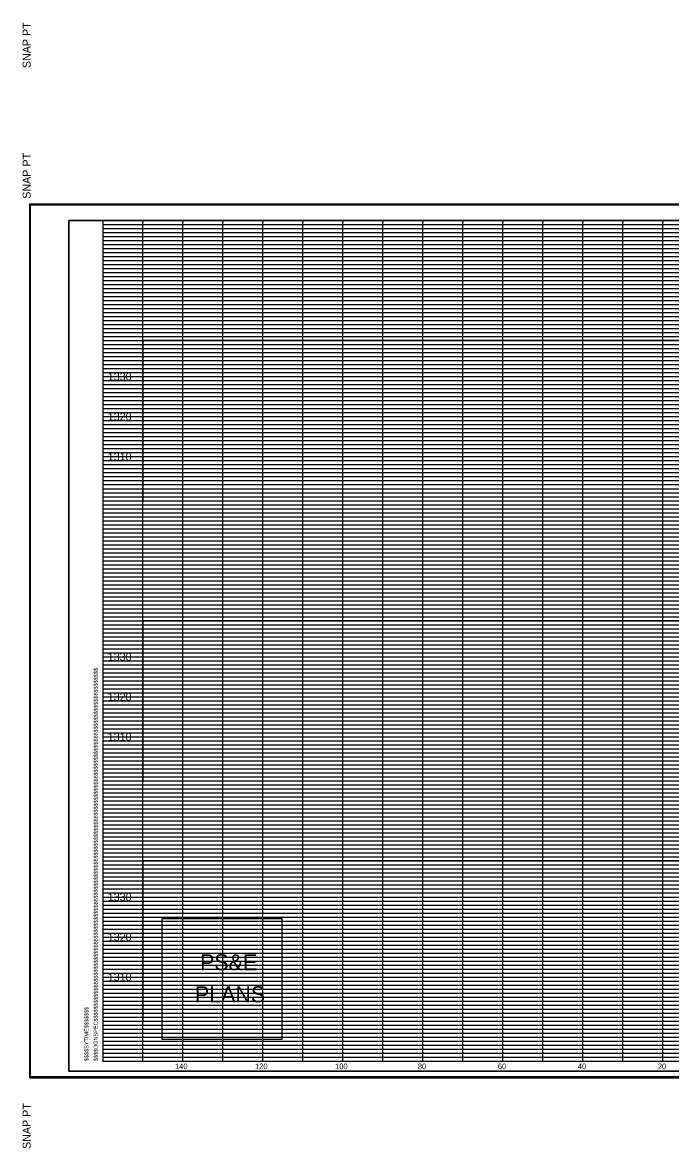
# Model space of a CAD drawing. Extents: x 130 to 1324, y -58 to 2657.
# Drawn here: x 979.9 to 1141.9, y 978.2 to 1259.4 of the extents above; entities that cross this region are included whole.
import ezdxf

# ---------------------------------------------------------------- set-up
doc = ezdxf.new("R2010")
doc.units = 0
for name, color, linetype in [('DESIGN - SCRATCH - User 2', 7, 'Continuous'), ('DESIGN - SHEET - Corner Text', 7, 'Continuous'), ('DESIGN - SHEET - Light Grid', 7, 'Continuous'), ('DESIGN - SHEET - Linework', 7, 'Continuous'), ('DESIGN - SHEET - Plot Shape', 7, 'Continuous'), ('DESIGN - TYPICAL - Finished Grade and Subgrade', 7, 'Continuous')]:
    doc.layers.add(name, color=color, linetype=linetype)

# ---------------------------------------------------------------- blocks, each defined once
blk = doc.blocks.new('XSTSHT')
at = {"layer": 'DESIGN - SHEET - Light Grid'}
for p, q in [((0, 20.9), (8, 20.9)), ((8, 20.9), (16, 20.9)), ((0, 20.8), (8, 20.8)), ((0, 20.7), (8, 20.7)), ((0, 20.6), (8, 20.6)), ((8, 20.8), (16, 20.8)), ((8, 20.7), (16, 20.7)), ((8, 20.6), (16, 20.6)), ((0, 20.5), (8, 20.5)), ((0, 20.4), (8, 20.4)), ((0, 20.3), (8, 20.3)), ((8, 20.5), (16, 20.5)), ((8, 20.4), (16, 20.4)), ((8, 20.3), (16, 20.3)), ((0, 20.2), (8, 20.2)), ((0, 20.1), (8, 20.1)), ((8, 20.2), (16, 20.2)), ((8, 20.1), (16, 20.1)), ((0, 19.9), (8, 19.9)), ((0, 19.8), (8, 19.8)), ((0, 19.7), (8, 19.7)), ((8, 19.9), (16, 19.9)), ((8, 19.8), (16, 19.8)), ((8, 19.7), (16, 19.7)), ((0, 19.6), (8, 19.6)), ((0, 19.5), (8, 19.5)), ((8, 19.6), (16, 19.6)), ((8, 19.5), (16, 19.5)), ((0, 19.4), (8, 19.4)), ((0, 19.3), (8, 19.3)), ((0, 19.2), (8, 19.2)), ((8, 19.4), (16, 19.4)), ((8, 19.3), (16, 19.3)), ((8, 19.2), (16, 19.2)), ((0, 19.1), (8, 19.1)), ((0, 18.9), (8, 18.9)), ((8, 19.1), (16, 19.1)), ((8, 18.9), (16, 18.9)), ((0, 18.8), (8, 18.8)), ((0, 18.7), (8, 18.7)), ((0, 18.6), (8, 18.6)), ((8, 18.8), (16, 18.8)), ((8, 18.7), (16, 18.7)), ((8, 18.6), (16, 18.6)), ((0, 18.5), (8, 18.5)), ((0, 18.4), (8, 18.4)), ((0, 18.3), (8, 18.3)), ((8, 18.5), (16, 18.5)), ((8, 18.4), (16, 18.4)), ((8, 18.3), (16, 18.3)), ((0, 18.2), (8, 18.2)), ((0, 18.1), (8, 18.1)), ((8, 18.2), (16, 18.2)), ((8, 18.1), (16, 18.1)), ((0, 17.9), (8, 17.9)), ((0, 17.8), (8, 17.8)), ((8, 17.9), (16, 17.9)), ((8, 17.8), (16, 17.8)), ((0, 17.7), (8, 17.7)), ((0, 17.6), (8, 17.6)), ((0, 17.5), (8, 17.5)), ((8, 17.7), (16, 17.7)), ((8, 17.6), (16, 17.6)), ((8, 17.5), (16, 17.5)), ((0, 17.4), (8, 17.4)), ((0, 17.3), (8, 17.3)), ((0, 17.2), (8, 17.2)), ((8, 17.4), (16, 17.4)), ((8, 17.3), (16, 17.3)), ((8, 17.2), (16, 17.2)), ((0, 17.1), (8, 17.1)), ((0, 16.9), (8, 16.9)), ((8, 17.1), (16, 17.1)), ((8, 16.9), (16, 16.9)), ((0, 16.8), (8, 16.8)), ((0, 16.7), (8, 16.7)), ((0, 16.6), (8, 16.6)), ((8, 16.8), (16, 16.8)), ((8, 16.7), (16, 16.7)), ((8, 16.6), (16, 16.6)), ((0, 16.5), (8, 16.5)), ((0, 16.4), (8, 16.4)), ((8, 16.5), (16, 16.5)), ((8, 16.4), (16, 16.4)), ((0, 16.3), (8, 16.3)), ((0, 16.2), (8, 16.2)), ((0, 16.1), (8, 16.1)), ((8, 16.3), (16, 16.3)), ((8, 16.2), (16, 16.2)), ((8, 16.1), (16, 16.1)), ((0, 15.9), (8, 15.9)), ((0, 15.8), (8, 15.8)), ((8, 15.9), (16, 15.9)), ((8, 15.8), (16, 15.8)), ((0, 15.7), (8, 15.7)), ((0, 15.6), (8, 15.6)), ((0, 15.5), (8, 15.5)), ((8, 15.7), (16, 15.7)), ((8, 15.6), (16, 15.6)), ((8, 15.5), (16, 15.5)), ((0, 15.4), (8, 15.4)), ((0, 15.3), (8, 15.3)), ((0, 15.2), (8, 15.2)), ((8, 15.4), (16, 15.4)), ((8, 15.3), (16, 15.3)), ((8, 15.2), (16, 15.2)), ((0, 15.1), (8, 15.1)), ((8, 15.1), (16, 15.1)), ((0, 14.9), (8, 14.9)), ((0, 14.8), (8, 14.8)), ((0, 14.7), (8, 14.7)), ((8, 14.9), (16, 14.9)), ((8, 14.8), (16, 14.8)), ((8, 14.7), (16, 14.7)), ((0, 14.6), (8, 14.6)), ((0, 14.5), (8, 14.5)), ((0, 14.4), (8, 14.4)), ((8, 14.6), (16, 14.6)), ((8, 14.5), (16, 14.5)), ((8, 14.4), (16, 14.4)), ((0, 14.3), (8, 14.3)), ((0, 14.2), (8, 14.2)), ((0, 14.1), (8, 14.1)), ((8, 14.3), (16, 14.3)), ((8, 14.2), (16, 14.2)), ((8, 14.1), (16, 14.1)), ((0, 13.9), (8, 13.9)), ((0, 13.8), (8, 13.8)), ((8, 13.9), (16, 13.9)), ((8, 13.8), (16, 13.8)), ((0, 13.7), (8, 13.7)), ((0, 13.6), (8, 13.6)), ((8, 13.7), (16, 13.7)), ((8, 13.6), (16, 13.6)), ((0, 13.5), (8, 13.5)), ((0, 13.4), (8, 13.4)), ((0, 13.3), (8, 13.3)), ((8, 13.5), (16, 13.5)), ((8, 13.4), (16, 13.4)), ((8, 13.3), (16, 13.3)), ((0, 13.2), (8, 13.2)), ((0, 13.1), (8, 13.1)), ((8, 13.2), (16, 13.2)), ((8, 13.1), (16, 13.1)), ((0, 12.9), (8, 12.9)), ((0, 12.8), (8, 12.8)), ((0, 12.7), (8, 12.7)), ((8, 12.9), (16, 12.9)), ((8, 12.8), (16, 12.8)), ((8, 12.7), (16, 12.7)), ((0, 12.6), (8, 12.6)), ((0, 12.5), (8, 12.5)), ((0, 12.4), (8, 12.4)), ((8, 12.6), (16, 12.6)), ((8, 12.5), (16, 12.5)), ((8, 12.4), (16, 12.4)), ((0, 12.3), (8, 12.3)), ((0, 12.2), (8, 12.2)), ((0, 12.1), (8, 12.1)), ((8, 12.3), (16, 12.3)), ((8, 12.2), (16, 12.2)), ((8, 12.1), (16, 12.1)), ((0, 11.9), (8, 11.9)), ((8, 11.9), (16, 11.9)), ((0, 11.8), (8, 11.8)), ((0, 11.7), (8, 11.7)), ((0, 11.6), (8, 11.6)), ((8, 11.8), (16, 11.8)), ((8, 11.7), (16, 11.7)), ((8, 11.6), (16, 11.6)), ((0, 11.5), (8, 11.5)), ((0, 11.4), (8, 11.4)), ((0, 11.3), (8, 11.3)), ((8, 11.5), (16, 11.5)), ((8, 11.4), (16, 11.4)), ((8, 11.3), (16, 11.3)), ((0, 11.2), (8, 11.2)), ((0, 11.1), (8, 11.1)), ((8, 11.2), (16, 11.2)), ((8, 11.1), (16, 11.1)), ((0, 10.9), (8, 10.9)), ((0, 10.8), (8, 10.8)), ((0, 10.7), (8, 10.7)), ((8, 10.9), (16, 10.9)), ((8, 10.8), (16, 10.8)), ((8, 10.7), (16, 10.7)), ((0, 10.6), (8, 10.6)), ((0, 10.5), (8, 10.5)), ((8, 10.6), (16, 10.6)), ((8, 10.5), (16, 10.5)), ((0, 10.4), (8, 10.4)), ((0, 10.3), (8, 10.3)), ((0, 10.2), (8, 10.2)), ((8, 10.4), (16, 10.4)), ((8, 10.3), (16, 10.3)), ((8, 10.2), (16, 10.2)), ((0, 10.1), (8, 10.1)), ((0, 9.9), (8, 9.9)), ((8, 10.1), (16, 10.1)), ((8, 9.9), (16, 9.9)), ((0, 9.8), (8, 9.8)), ((0, 9.7), (8, 9.7)), ((0, 9.6), (8, 9.6)), ((8, 9.8), (16, 9.8)), ((8, 9.7), (16, 9.7)), ((8, 9.6), (16, 9.6)), ((0, 9.5), (8, 9.5)), ((0, 9.4), (8, 9.4)), ((0, 9.3), (8, 9.3)), ((8, 9.5), (16, 9.5)), ((8, 9.4), (16, 9.4)), ((8, 9.3), (16, 9.3)), ((0, 9.2), (8, 9.2)), ((0, 9.1), (8, 9.1)), ((8, 9.2), (16, 9.2)), ((8, 9.1), (16, 9.1)), ((0, 8.9), (8, 8.9)), ((0, 8.8), (8, 8.8)), ((8, 8.9), (16, 8.9)), ((8, 8.8), (16, 8.8)), ((0, 8.7), (8, 8.7)), ((0, 8.6), (8, 8.6)), ((0, 8.5), (8, 8.5)), ((8, 8.7), (16, 8.7)), ((8, 8.6), (16, 8.6)), ((8, 8.5), (16, 8.5)), ((0, 8.4), (8, 8.4)), ((0, 8.3), (8, 8.3)), ((0, 8.2), (8, 8.2)), ((8, 8.4), (16, 8.4)), ((8, 8.3), (16, 8.3)), ((8, 8.2), (16, 8.2)), ((0, 8.1), (8, 8.1)), ((0, 7.9), (8, 7.9)), ((8, 8.1), (16, 8.1)), ((8, 7.9), (16, 7.9)), ((0, 7.8), (8, 7.8)), ((0, 7.7), (8, 7.7)), ((0, 7.6), (8, 7.6)), ((8, 7.8), (16, 7.8)), ((8, 7.7), (16, 7.7)), ((8, 7.6), (16, 7.6)), ((0, 7.5), (8, 7.5)), ((0, 7.4), (8, 7.4)), ((8, 7.5), (16, 7.5)), ((8, 7.4), (16, 7.4)), ((0, 7.3), (8, 7.3)), ((0, 7.2), (8, 7.2)), ((0, 7.1), (8, 7.1)), ((8, 7.3), (16, 7.3)), ((8, 7.2), (16, 7.2)), ((8, 7.1), (16, 7.1)), ((0, 6.9), (8, 6.9)), ((0, 6.8), (8, 6.8)), ((8, 6.9), (16, 6.9)), ((8, 6.8), (16, 6.8)), ((0, 6.7), (8, 6.7)), ((0, 6.6), (8, 6.6)), ((0, 6.5), (8, 6.5)), ((8, 6.7), (16, 6.7)), ((8, 6.6), (16, 6.6)), ((8, 6.5), (16, 6.5)), ((0, 6.4), (8, 6.4)), ((0, 6.3), (8, 6.3)), ((0, 6.2), (8, 6.2)), ((8, 6.4), (16, 6.4)), ((8, 6.3), (16, 6.3)), ((8, 6.2), (16, 6.2)), ((0, 6.1), (8, 6.1)), ((8, 6.1), (16, 6.1)), ((0, 5.9), (8, 5.9)), ((0, 5.8), (8, 5.8)), ((0, 5.7), (8, 5.7)), ((8, 5.9), (16, 5.9)), ((8, 5.8), (16, 5.8)), ((8, 5.7), (16, 5.7)), ((0, 5.6), (8, 5.6)), ((0, 5.5), (8, 5.5)), ((0, 5.4), (8, 5.4)), ((8, 5.6), (16, 5.6)), ((8, 5.5), (16, 5.5)), ((8, 5.4), (16, 5.4)), ((0, 5.3), (8, 5.3)), ((0, 5.2), (8, 5.2)), ((0, 5.1), (8, 5.1)), ((8, 5.3), (16, 5.3)), ((8, 5.2), (16, 5.2)), ((8, 5.1), (16, 5.1)), ((0, 4.9), (8, 4.9)), ((0, 4.8), (8, 4.8)), ((8, 4.9), (16, 4.9)), ((8, 4.8), (16, 4.8)), ((0, 4.7), (8, 4.7)), ((0, 4.6), (8, 4.6)), ((8, 4.7), (16, 4.7)), ((8, 4.6), (16, 4.6)), ((0, 4.5), (8, 4.5)), ((0, 4.4), (8, 4.4)), ((0, 4.3), (8, 4.3)), ((8, 4.5), (16, 4.5)), ((8, 4.4), (16, 4.4)), ((8, 4.3), (16, 4.3)), ((0, 4.2), (8, 4.2)), ((0, 4.1), (8, 4.1)), ((8, 4.2), (16, 4.2)), ((8, 4.1), (16, 4.1)), ((0, 3.9), (8, 3.9)), ((0, 3.8), (8, 3.8)), ((0, 3.7), (8, 3.7)), ((8, 3.9), (16, 3.9)), ((8, 3.8), (16, 3.8)), ((8, 3.7), (16, 3.7)), ((0, 3.6), (8, 3.6)), ((0, 3.5), (8, 3.5)), ((0, 3.4), (8, 3.4)), ((8, 3.6), (16, 3.6)), ((8, 3.5), (16, 3.5)), ((8, 3.4), (16, 3.4)), ((0, 3.3), (8, 3.3)), ((0, 3.2), (8, 3.2)), ((0, 3.1), (8, 3.1)), ((8, 3.3), (16, 3.3)), ((8, 3.2), (16, 3.2)), ((8, 3.1), (16, 3.1)), ((0, 2.9), (8, 2.9)), ((8, 2.9), (16, 2.9)), ((0, 2.8), (8, 2.8)), ((0, 2.7), (8, 2.7)), ((0, 2.6), (8, 2.6)), ((8, 2.8), (16, 2.8)), ((8, 2.7), (16, 2.7)), ((8, 2.6), (16, 2.6)), ((0, 2.5), (8, 2.5)), ((0, 2.4), (8, 2.4)), ((0, 2.3), (8, 2.3)), ((8, 2.5), (16, 2.5)), ((8, 2.4), (16, 2.4)), ((8, 2.3), (16, 2.3)), ((0, 2.2), (8, 2.2)), ((0, 2.1), (8, 2.1)), ((8, 2.2), (16, 2.2)), ((8, 2.1), (16, 2.1)), ((0, 1.9), (8, 1.9)), ((0, 1.8), (8, 1.8)), ((0, 1.7), (8, 1.7)), ((8, 1.9), (16, 1.9)), ((8, 1.8), (16, 1.8)), ((8, 1.7), (16, 1.7)), ((0, 1.6), (8, 1.6)), ((0, 1.5), (8, 1.5)), ((8, 1.6), (16, 1.6)), ((8, 1.5), (16, 1.5)), ((0, 1.4), (8, 1.4)), ((0, 1.3), (8, 1.3)), ((0, 1.2), (8, 1.2)), ((8, 1.4), (16, 1.4)), ((8, 1.3), (16, 1.3)), ((8, 1.2), (16, 1.2)), ((0, 1.1), (8, 1.1)), ((0, 0.9), (8, 0.9)), ((8, 1.1), (16, 1.1)), ((8, 0.9), (16, 0.9)), ((0, 0.8), (8, 0.8)), ((0, 0.7), (8, 0.7)), ((0, 0.6), (8, 0.6)), ((8, 0.8), (16, 0.8)), ((8, 0.7), (16, 0.7)), ((8, 0.6), (16, 0.6)), ((0, 0.5), (8, 0.5)), ((0, 0.4), (8, 0.4)), ((0, 0.3), (8, 0.3)), ((8, 0.5), (16, 0.5)), ((8, 0.4), (16, 0.4)), ((8, 0.3), (16, 0.3)), ((0, 0.2), (8, 0.2)), ((0, 0.1), (8, 0.1)), ((8, 0.2), (16, 0.2)), ((8, 0.1), (16, 0.1))]:
    blk.add_line(p, q, dxfattribs=at)
at = {"layer": 'DESIGN - SHEET - Linework'}
for p, q in [((-1.823, -0.414), (-1.823, 21.414)), ((-1.823, 21.414), (32.217, 21.414)), ((1, 0), (1, 21)), ((2, 0), (2, 21)), ((3, 0), (3, 21)), ((4, 0), (4, 21)), ((5, 0), (5, 21)), ((6, 0), (6, 21)), ((7, 0), (7, 21)), ((8, 0), (8, 21)), ((9, 0), (9, 21)), ((10, 0), (10, 21)), ((11, 0), (11, 21)), ((12, 0), (12, 21)), ((13, 0), (13, 21)), ((14, 0), (14, 21)), ((0, 20), (28, 20)), ((0, 19), (32, 19)), ((0, 18), (32, 18)), ((0, 17), (32, 17)), ((0, 16), (32, 16)), ((0, 15), (32, 15)), ((0, 14), (32, 14)), ((0, 13), (32, 13)), ((0, 12), (32, 12)), ((0, 11), (32, 11)), ((0, 10), (32, 10)), ((0, 9), (32, 9)), ((0, 8), (32, 8)), ((0, 7), (32, 7)), ((0, 6), (32, 6)), ((0, 5), (32, 5)), ((0, 4), (32, 4)), ((0, 3), (32, 3)), ((0, 2), (32, 2)), ((0, 1), (32, 1)), ((-1.823, -0.414), (32.217, -0.414))]:
    blk.add_line(p, q, dxfattribs=at)
blk.add_lwpolyline([(0, 21), (0, 0), (32, 0), (32, 21), (0, 21)], dxfattribs=at)
at = {"layer": 'DESIGN - SHEET - Plot Shape'}
for points in [[(-1.803, 21.394), (32.197, 21.394), (32.197, -0.394), (-1.803, -0.394)], [(-0.85, 21), (32, 21), (32, -0.25), (-0.85, -0.25)]]:
    blk.add_lwpolyline(points, close=True, dxfattribs=at)
at = {"layer": 'DESIGN - SHEET - Corner Text'}
for s, height, p in [('  SNAP PT', 0.2, (-1.803, 21.394)), ('$$$$DGNSPEC$$$$$$$$$$$$$$$$$$$$$$$$$$$$$$$$$$$$$$$$$$$$$$$$$$$$$$$$$$$$$$$$$$$$$$$$$$$$$$$$$$$$$$$$$$$$$$$$$$$$$$$$$$$$$$$$$$$', 0.100002, (-0.126, 0)), ('$$$$SYTIME$$$$$$$', 0.1, (-0.358, 0)), ('SNAP PT  ', 0.2, (-1.803, -2.194))]:
    blk.add_text(s, height=height, rotation=90, dxfattribs=at).set_placement(p)

msp = doc.modelspace()

# ---------------------------------------------------------------- linework, layer by layer
at = {"layer": 'DESIGN - SCRATCH - User 2'}
for points in [[(1010, 1140), (1310, 1140), (1310, 1180), (1010, 1180)], [(1010, 1070), (1310, 1070), (1310, 1110), (1010, 1110)], [(1010, 1010), (1310, 1010), (1310, 1050), (1010, 1050)]]:
    msp.add_lwpolyline(points, close=True, dxfattribs=at)
at = {"layer": 'DESIGN - SHEET - Corner Text'}
msp.add_lwpolyline([(1014.8, 1035.52), (1014.8, 1005.52), (1044.8, 1005.52), (1044.8, 1035.52)], close=True, dxfattribs=at)
at = {"layer": 'DESIGN - SHEET - Plot Shape'}
msp.add_lwpolyline([(991.5, 997.5), (1320, 997.5), (1320, 1210), (991.5, 1210)], close=True, dxfattribs=at)

# ---------------------------------------------------------------- block references
at = {"layer": 'DESIGN - TYPICAL - Finished Grade and Subgrade', "xscale": 10, "yscale": 10}
for p in [(1000, 1270), (1000, 1000)]:
    msp.add_blockref('XSTSHT', p, dxfattribs=at)

# ---------------------------------------------------------------- texts
at = {"layer": 'DESIGN - SHEET - Corner Text'}
for s, height, p in [('1330', 2, (1001.25, 1170)), ('1320', 2, (1001.25, 1160)), ('1310', 2, (1001.25, 1150)), ('1330', 2, (1001.25, 1100)), ('1320', 2, (1001.25, 1090)), ('1310', 2, (1001.25, 1080)), ('1330', 2, (1001.25, 1040)), ('1320', 2, (1001.25, 1030)), ('PS&E', 4, (1024.32, 1022.7)), ('1310', 2, (1001.25, 1020)), ('PLANS', 4, (1023.04, 1014.7)), ('140', 1.4, (1018.06, 998)), ('120', 1.4, (1038.06, 998)), ('100', 1.4, (1058.06, 998)), ('80', 1.4, (1078.74, 998)), ('60', 1.4, (1098.74, 998)), ('40', 1.4, (1118.74, 998)), ('20', 1.4, (1138.74, 998))]:
    msp.add_text(s, height=height, dxfattribs=at).set_placement(p)

doc.saveas('drawing.dxf')
